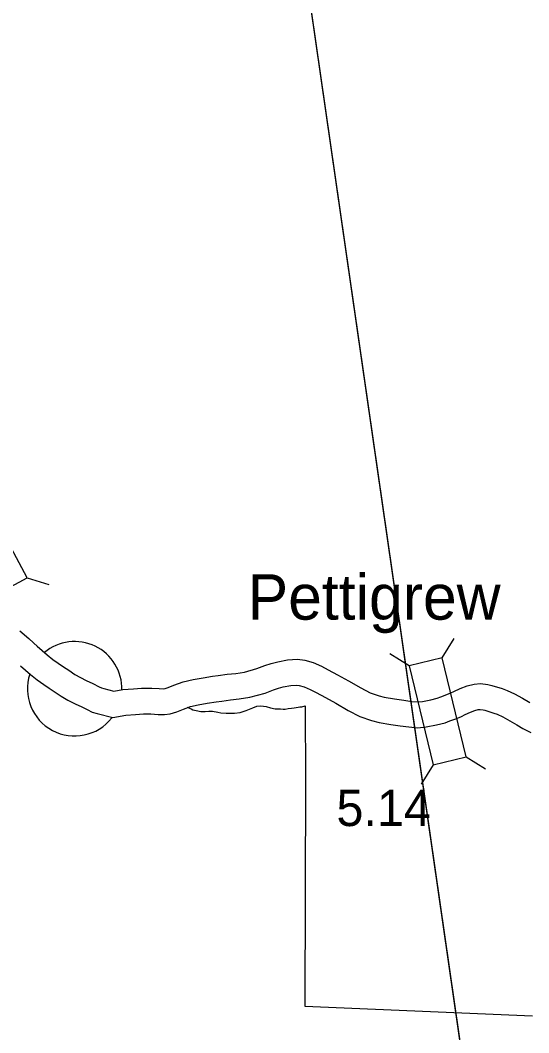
# Model space of a CAD drawing. Extents: x 0 to 3171, y 0 to 2059.
# Drawn here: x 528.3 to 646.7, y 1414.6 to 1650.4 of the extents above; entities that cross this region are included whole.
import ezdxf

# ---------------------------------------------------------------- set-up
doc = ezdxf.new("R2010")
doc.units = 0
for name, color, linetype in [('Default', 7, 'Continuous'), ('Level 10', 7, 'Continuous'), ('Level 20', 7, 'Continuous'), ('Level 24', 7, 'Continuous'), ('Level 58', 7, 'Continuous'), ('Level 8', 7, 'Continuous')]:
    doc.layers.add(name, color=color, linetype=linetype)

msp = doc.modelspace()

# ---------------------------------------------------------------- linework, layer by layer
at = {"layer": 'Default'}
for points in [[(273.27, 1355.18), (654.18, 1249.83), (565, 1868.47)], [(641.56, 1337.33), (565, 1868.47)]]:
    msp.add_lwpolyline(points, dxfattribs=at)
msp.add_circle((410.95, 1647.45), 386.47, dxfattribs=at)
msp.add_circle((410.95, 1647.45), 386.47, dxfattribs=at)
at = {"layer": 'Level 10'}
for points in [[(528.2, 1508.26), (530.24, 1506.48), (532.33, 1504.52)], [(528.2, 1508.26), (530.24, 1506.48), (532.33, 1504.52)], [(532.21, 1504.63), (534.51, 1502.68), (535.84, 1501.59), (537.12, 1500.69), (538.35, 1499.87), (539.56, 1499.06), (540.99, 1498.08), (542.29, 1497.35), (543.62, 1496.64), (545.15, 1496), (546.64, 1495.22), (547.17, 1494.94), (547.71, 1494.81), (550.05, 1494.18), (552.18, 1494.57), (554.63, 1494.7), (556.47, 1494.88), (556.96, 1494.91), (558.92, 1494.87), (560.59, 1494.77), (561.55, 1494.76), (562.01, 1494.81), (562.71, 1495.01), (564.04, 1495.57), (566.2, 1496.39), (568.57, 1496.91), (570.83, 1497.31), (573.08, 1497.64), (574.38, 1497.81), (576.47, 1498.11), (578.46, 1498.33), (580.52, 1498.64), (583.37, 1499.43), (585.23, 1500.17), (586.7, 1500.65), (588.24, 1501.04), (590.51, 1501.45), (592.86, 1501.63), (594.51, 1501.42), (596.47, 1500.83), (598.39, 1499.98), (599.94, 1499.16), (602.18, 1498.01), (604.75, 1496.61), (607.55, 1494.95), (609.78, 1493.82), (611.83, 1493.07), (613.05, 1492.76), (615.46, 1492.37), (617.59, 1492.08), (619.44, 1491.81), (620.84, 1491.68), (621.93, 1491.78), (623.91, 1492.2), (625.39, 1492.56), (626.22, 1492.9), (627.58, 1493.37), (628.52, 1493.76), (629.27, 1494.12), (630.73, 1494.82), (632.36, 1495.46), (633.94, 1495.81), (635.47, 1495.97), (637.14, 1495.74), (638.06, 1495.53), (640.51, 1494.77), (641.63, 1494.36), (643.35, 1493.56), (645.23, 1492.55), (646.97, 1491.54)], [(532.21, 1504.63), (534.51, 1502.68), (535.84, 1501.59), (537.12, 1500.69), (538.35, 1499.87), (539.56, 1499.06), (540.99, 1498.08), (542.29, 1497.35), (543.62, 1496.64), (545.15, 1496), (546.64, 1495.22), (547.17, 1494.94), (547.71, 1494.81), (550.05, 1494.18), (552.18, 1494.57), (554.63, 1494.7), (556.47, 1494.88), (556.96, 1494.91), (558.92, 1494.87), (560.59, 1494.77), (561.55, 1494.76), (562.01, 1494.81), (562.71, 1495.01), (564.04, 1495.57), (566.2, 1496.39), (568.57, 1496.91), (570.83, 1497.31), (573.08, 1497.64), (574.38, 1497.81), (576.47, 1498.11), (578.46, 1498.33), (580.52, 1498.64), (583.37, 1499.43), (585.23, 1500.17), (586.7, 1500.65), (588.24, 1501.04), (590.51, 1501.45), (592.86, 1501.63), (594.51, 1501.42), (596.47, 1500.83), (598.39, 1499.98), (599.94, 1499.16), (602.18, 1498.01), (604.75, 1496.61), (607.55, 1494.95), (609.78, 1493.82), (611.83, 1493.07), (613.05, 1492.76), (615.46, 1492.37), (617.59, 1492.08), (619.44, 1491.81), (620.84, 1491.68), (621.93, 1491.78), (623.91, 1492.2), (625.39, 1492.56), (626.22, 1492.9), (627.58, 1493.37), (628.52, 1493.76), (629.27, 1494.12), (630.73, 1494.82), (632.36, 1495.46), (633.94, 1495.81), (635.47, 1495.97), (637.14, 1495.74), (638.06, 1495.53), (640.51, 1494.77), (641.63, 1494.36), (643.35, 1493.56), (645.23, 1492.55), (646.97, 1491.54)], [(528.33, 1500.05), (530.67, 1498.07), (532.21, 1496.81), (533.73, 1495.74), (535.02, 1494.88), (536.2, 1494.09), (537.81, 1492.99), (539.39, 1492.09), (541.05, 1491.21), (542.6, 1490.56), (543.86, 1489.9), (545.01, 1489.3), (546.19, 1489), (549.8, 1488.03), (552.89, 1488.6), (555.08, 1488.72), (556.95, 1488.9), (557.09, 1488.91), (558.68, 1488.88), (560.37, 1488.78), (561.84, 1488.75), (563.18, 1488.91), (564.71, 1489.34), (566.26, 1489.99), (567.92, 1490.62), (569.74, 1491.02), (571.79, 1491.39), (573.89, 1491.7), (575.18, 1491.86), (577.23, 1492.16), (579.23, 1492.38), (581.77, 1492.76), (585.29, 1493.74), (587.27, 1494.52), (588.38, 1494.88), (589.52, 1495.18), (591.27, 1495.49), (592.71, 1495.6), (593.26, 1495.53), (594.38, 1495.2), (595.77, 1494.58), (597.17, 1493.84), (599.37, 1492.71), (601.79, 1491.39), (604.66, 1489.69), (607.39, 1488.3), (610.06, 1487.33), (611.83, 1486.88), (614.57, 1486.44), (616.75, 1486.14), (618.73, 1485.85), (620.84, 1485.66), (622.83, 1485.84), (625.23, 1486.35), (627.26, 1486.84), (628.35, 1487.29), (629.7, 1487.75), (630.99, 1488.29), (631.88, 1488.72), (633.12, 1489.31), (634.13, 1489.71), (634.9, 1489.88), (635.37, 1489.93), (636.05, 1489.84), (636.49, 1489.73), (638.59, 1489.09), (639.31, 1488.82), (640.66, 1488.19), (642.3, 1487.31), (643.91, 1486.37), (645.35, 1485.51), (647.14, 1484.54)], [(528.33, 1500.05), (530.67, 1498.07), (532.21, 1496.81), (533.73, 1495.74), (535.02, 1494.88), (536.2, 1494.09), (537.81, 1492.99), (539.39, 1492.09), (541.05, 1491.21), (542.6, 1490.56), (543.86, 1489.9), (545.01, 1489.3), (546.19, 1489), (549.8, 1488.03), (552.89, 1488.6), (555.08, 1488.72), (556.95, 1488.9), (557.09, 1488.91), (558.68, 1488.88), (560.37, 1488.78), (561.84, 1488.75), (563.18, 1488.91), (564.71, 1489.34), (566.26, 1489.99), (567.92, 1490.62), (569.74, 1491.02), (571.79, 1491.39), (573.89, 1491.7), (575.18, 1491.86), (577.23, 1492.16), (579.23, 1492.38), (581.77, 1492.76), (585.29, 1493.74), (587.27, 1494.52), (588.38, 1494.88), (589.52, 1495.18), (591.27, 1495.49), (592.71, 1495.6), (593.26, 1495.53), (594.38, 1495.2), (595.77, 1494.58), (597.17, 1493.84), (599.37, 1492.71), (601.79, 1491.39), (604.66, 1489.69), (607.39, 1488.3), (610.06, 1487.33), (611.83, 1486.88), (614.57, 1486.44), (616.75, 1486.14), (618.73, 1485.85), (620.84, 1485.66), (622.83, 1485.84), (625.23, 1486.35), (627.26, 1486.84), (628.35, 1487.29), (629.7, 1487.75), (630.99, 1488.29), (631.88, 1488.72), (633.12, 1489.31), (634.13, 1489.71), (634.9, 1489.88), (635.37, 1489.93), (636.05, 1489.84), (636.49, 1489.73), (638.59, 1489.09), (639.31, 1488.82), (640.66, 1488.19), (642.3, 1487.31), (643.91, 1486.37), (645.35, 1485.51), (647.14, 1484.54)]]:
    msp.add_lwpolyline(points, dxfattribs=at)
at = {"layer": 'Level 20'}
for p, q in [((529.89, 1520.58), (534.95, 1519.06)), ((529.89, 1520.58), (534.95, 1519.06)), ((626.56, 1501.97), (629.32, 1506.48)), ((626.56, 1501.97), (629.32, 1506.48)), ((618.86, 1500.12), (614.36, 1502.88)), ((618.86, 1500.12), (614.36, 1502.88)), ((632.12, 1478.87), (636.62, 1476.11)), ((632.12, 1478.87), (636.62, 1476.11)), ((624.42, 1477.02), (621.66, 1472.52)), ((624.42, 1477.02), (621.66, 1472.52))]:
    msp.add_line(p, q, dxfattribs=at)
for points in [[(526.13, 1527.55), (505.22, 1516.28), (508.97, 1509.3), (529.89, 1520.58)], [(526.13, 1527.55), (505.22, 1516.28), (508.97, 1509.3), (529.89, 1520.58)], [(618.86, 1500.12), (624.42, 1477.02), (632.12, 1478.87), (626.56, 1501.97)], [(618.86, 1500.12), (624.42, 1477.02), (632.12, 1478.87), (626.56, 1501.97)]]:
    msp.add_lwpolyline(points, close=True, dxfattribs=at)
at = {"layer": 'Level 24'}
for start, end in [(358.5805, 129.8711), (358.5805, 129.8711), (161.9711, 321.7212), (161.9711, 321.7212)]:
    msp.add_arc((540.94, 1494.75), 11, start, end, dxfattribs=at)
at = {"layer": 'Level 8'}
msp.add_lwpolyline([(567.05, 1490.42), (567.29, 1490.38), (568.08, 1490.06), (568.48, 1489.84), (569.24, 1489.66), (570.36, 1489.48), (571.36, 1489.42), (572.22, 1489.56), (573.01, 1489.55), (574.29, 1489.27), (575.01, 1489.15), (576.23, 1489.09), (577.28, 1489.03), (578.18, 1489.03), (579.5, 1489.25), (580.91, 1489.71), (582.43, 1490.32), (583.35, 1490.66), (584.32, 1490.76), (585.52, 1490.62), (586.54, 1490.32), (587.62, 1490.1), (588.83, 1490.06), (588.85, 1490.06), (589.53, 1490), (589.93, 1490.02), (590.67, 1490.18), (591.41, 1490.2), (592.05, 1490.28), (592.53, 1490.35), (593, 1490.47), (593.38, 1490.53), (593.84, 1490.57), (594.64, 1490.77), (594.72, 1473.53), (594.55, 1420.82), (647.59, 1418.57)], dxfattribs=at)
msp.add_lwpolyline([(567.05, 1490.42), (567.29, 1490.38), (568.08, 1490.06), (568.48, 1489.84), (569.24, 1489.66), (570.36, 1489.48), (571.36, 1489.42), (572.22, 1489.56), (573.01, 1489.55), (574.29, 1489.27), (575.01, 1489.15), (576.23, 1489.09), (577.28, 1489.03), (578.18, 1489.03), (579.5, 1489.25), (580.91, 1489.71), (582.43, 1490.32), (583.35, 1490.66), (584.32, 1490.76), (585.52, 1490.62), (586.54, 1490.32), (587.62, 1490.1), (588.83, 1490.06), (588.85, 1490.06), (589.53, 1490), (589.93, 1490.02), (590.67, 1490.18), (591.41, 1490.2), (592.05, 1490.28), (592.53, 1490.35), (593, 1490.47), (593.38, 1490.53), (593.84, 1490.57), (594.64, 1490.77), (594.72, 1473.53), (594.55, 1420.82), (647.59, 1418.57)], dxfattribs=at)

# ---------------------------------------------------------------- texts
at = {"layer": 'Level 24'}
msp.add_text('Pettigrew', height=10.56, dxfattribs=at).set_placement((581.25, 1510.84))
msp.add_text('Pettigrew', height=10.56, dxfattribs=at).set_placement((581.25, 1510.84))
at = {"layer": 'Level 58'}
msp.add_text('5.14', height=8.448, dxfattribs=at).set_placement((601.91, 1462.77))
msp.add_text('5.14', height=8.448, dxfattribs=at).set_placement((601.91, 1462.77))

doc.saveas('drawing.dxf')
